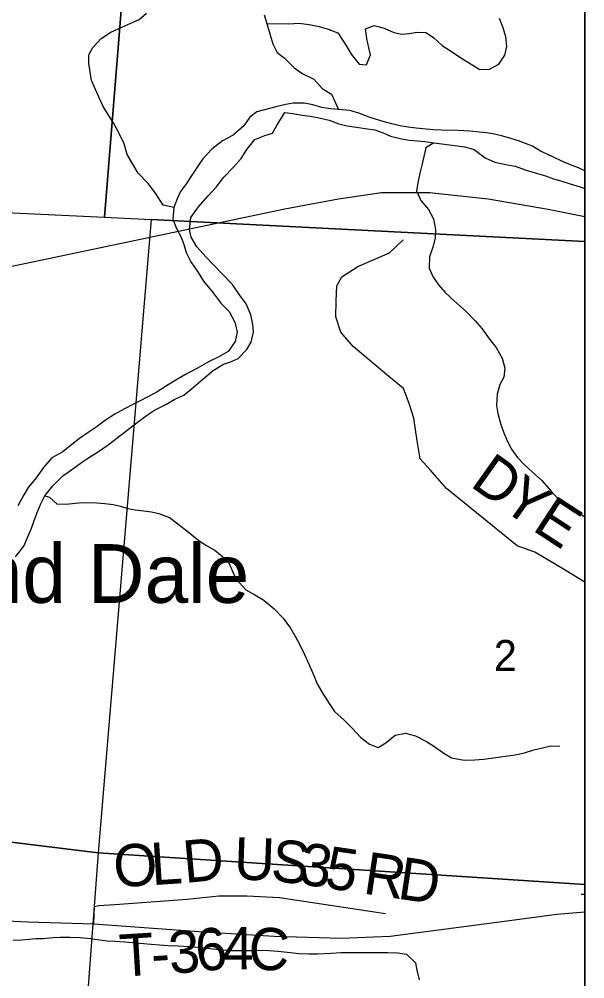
# Model space of a CAD drawing. Extents: x 5.6 to 39.6, y 0.7 to 22.7.
# Drawn here: x 14.292 to 15.052, y 19.81 to 21.1 of the extents above; entities that cross this region are included whole.
import ezdxf

# ---------------------------------------------------------------- set-up
doc = ezdxf.new("R2010")
doc.units = 0
doc.layers.add('Default', color=7, linetype='Continuous')
doc.layers.add('SH_Data', color=7, linetype='Continuous')

msp = doc.modelspace()

# ---------------------------------------------------------------- linework, layer by layer
at = {"layer": 'Default'}
for p, q in [((15.0518, 19.9373), (15.0518, 20.8015)), ((15.0518, 18.9873), (15.0518, 19.9373))]:
    msp.add_line(p, q, dxfattribs=at)
for points in [[(15.0518, 18.0251), (15.0518, 21.7074), (8.2518, 21.7074), (8.2518, 18.5322)], [(15.0518, 18.0251), (15.0518, 21.7074), (8.2518, 21.7074), (8.2518, 18.5322)], [(15.0518, 18.0251), (15.0518, 21.7074), (10.4881, 21.7074)], [(13.5074, 21.7074), (13.4593, 20.8788), (14.4061, 20.8339), (14.4767, 21.7074)], [(14.4767, 21.7074), (14.4061, 20.8339), (14.469, 20.831), (15.0518, 20.8015)], [(15.0518, 20.8015), (15.0518, 21.7074), (14.4767, 21.7074)], [(14.4994, 20.8472), (14.485, 20.8504), (14.4746, 20.8661), (14.4649, 20.8791), (14.4515, 20.8933), (14.4441, 20.9051), (14.4367, 20.9185), (14.4327, 20.9326), (14.426, 20.9463), (14.4186, 20.96), (14.4127, 20.9696), (14.4045, 20.9826), (14.3994, 20.9937), (14.3887, 21.0177), (14.3869, 21.0295), (14.3852, 21.0405), (14.3853, 21.0522), (14.3904, 21.062), (14.4019, 21.0744), (14.4148, 21.0829), (14.4297, 21.0892), (14.4414, 21.0947), (14.4529, 21.0999), (14.4628, 21.1081)], [(14.6206, 21.1061), (14.6246, 21.0942), (14.6286, 21.0805), (14.6326, 21.0672), (14.6381, 21.0554), (14.6479, 21.0481), (14.661, 21.0346), (14.673, 21.0269), (14.6876, 21.0195), (14.6989, 21.0072), (14.7113, 20.9995), (14.7208, 20.9789)], [(14.6246, 21.0942), (14.6541, 21.0939), (14.6674, 21.0948), (14.6813, 21.0931), (14.6949, 21.0903), (14.707, 21.0868), (14.7198, 21.0817), (14.7313, 21.0637), (14.7376, 21.053), (14.7485, 21.0396), (14.7583, 21.0387), (14.7637, 21.0523), (14.7616, 21.0618), (14.7587, 21.0743), (14.757, 21.0873), (14.7688, 21.0917), (14.782, 21.0881), (14.7951, 21.0822), (14.8057, 21.0802), (14.8156, 21.0808), (14.8266, 21.0826), (14.8379, 21.0824), (14.8484, 21.0755), (14.86, 21.0647), (14.8713, 21.0578), (14.8837, 21.0489), (14.9108, 21.0326), (14.9236, 21.0329), (14.9362, 21.0399), (14.9443, 21.0516), (14.9471, 21.0633), (14.9457, 21.0766), (14.9421, 21.0887), (14.9373, 21.1009)], [(15.0518, 20.8965), (15.0432, 20.9002), (15.0327, 20.9045), (15.0225, 20.9084), (15.0078, 20.9154), (14.9924, 20.9228), (14.9815, 20.9294), (14.9626, 20.9368), (14.9524, 20.94), (14.9415, 20.9428), (14.9302, 20.9456), (14.9196, 20.9472), (14.9097, 20.9481), (14.8973, 20.9498), (14.8814, 20.9507), (14.8594, 20.951), (14.8485, 20.9515), (14.8386, 20.9524), (14.825, 20.9537), (14.8144, 20.955), (14.8031, 20.957), (14.7925, 20.9594), (14.782, 20.9622), (14.7718, 20.9654), (14.762, 20.9685), (14.748, 20.974), (14.736, 20.9772), (14.7208, 20.9789), (14.7099, 20.9798), (14.6985, 20.9815), (14.6861, 20.985), (14.6748, 20.9871), (14.66, 20.9873), (14.6501, 20.9855), (14.6384, 20.983), (14.611, 20.9758), (14.6015, 20.9683), (14.5934, 20.9567), (14.5793, 20.9443), (14.5648, 20.9366), (14.5503, 20.9254), (14.5384, 20.9123), (14.5307, 20.9014), (14.5237, 20.8905)], [(14.2866, 20.3775), (14.2978, 20.3921), (14.3028, 20.4034), (14.3075, 20.4148), (14.311, 20.425), (14.3157, 20.437), (14.32, 20.448), (14.3262, 20.4596), (14.3366, 20.4728), (14.3504, 20.4866), (14.3618, 20.4945), (14.3752, 20.5045), (14.3848, 20.5108), (14.3981, 20.519), (14.4111, 20.5279), (14.4229, 20.5369), (14.4386, 20.5492), (14.452, 20.5596), (14.4627, 20.5675), (14.4733, 20.5745), (14.4886, 20.5823), (14.5008, 20.5894), (14.5129, 20.5949), (14.5229, 20.6031), (14.5382, 20.6162), (14.5523, 20.6281), (14.5661, 20.6367), (14.5756, 20.6396), (14.5858, 20.644), (14.5977, 20.6564), (14.6035, 20.6661), (14.6063, 20.6801), (14.6057, 20.69), (14.6028, 20.7029), (14.5966, 20.7178), (14.5876, 20.7297), (14.5783, 20.7434), (14.563, 20.7592), (14.5529, 20.7699), (14.5428, 20.7803), (14.5301, 20.7941), (14.5227, 20.8074), (14.5206, 20.8173), (14.5223, 20.8336), (14.5327, 20.8479), (14.5457, 20.8629), (14.5561, 20.8745), (14.5668, 20.888), (14.5795, 20.9011), (14.5899, 20.9131), (14.5976, 20.9251), (14.6083, 20.9383), (14.6216, 20.9438), (14.6319, 20.9471), (14.6385, 20.958), (14.6485, 20.9749), (14.6595, 20.9733), (14.6719, 20.9712), (14.6825, 20.9699), (14.6927, 20.9679), (14.7082, 20.9643), (14.721, 20.9596), (14.7323, 20.9568), (14.7448, 20.9551), (14.7565, 20.9534), (14.7697, 20.9514), (14.7806, 20.9475), (14.7904, 20.9428), (14.8036, 20.9396), (14.8157, 20.9375), (14.8267, 20.9366), (14.8369, 20.9358), (14.849, 20.9341)], [(14.849, 20.9341), (14.8383, 20.9274), (14.8327, 20.904), (14.83, 20.893), (14.8276, 20.8824), (14.8255, 20.8696), (14.8314, 20.8566), (14.8419, 20.8443), (14.8482, 20.8317), (14.851, 20.8177), (14.8505, 20.8063), (14.8481, 20.795), (14.843, 20.7806), (14.8424, 20.7655), (14.848, 20.7533), (14.855, 20.743), (14.864, 20.7326), (14.8767, 20.7211), (14.8925, 20.7072), (14.9044, 20.6946), (14.9138, 20.6838), (14.9238, 20.6701), (14.9328, 20.659), (14.9409, 20.6445), (14.9445, 20.6312), (14.9429, 20.619), (14.9375, 20.6093), (14.9339, 20.5964), (14.933, 20.5809), (14.9347, 20.5702), (14.9391, 20.5554), (14.9431, 20.5444), (14.9479, 20.5326), (14.9531, 20.5223), (14.9613, 20.5112), (14.9702, 20.5016), (14.9811, 20.492), (14.9942, 20.48), (15.0062, 20.4663), (15.0196, 20.4517), (15.0343, 20.442), (15.0467, 20.4343), (15.0518, 20.4314)], [(14.849, 20.9341), (14.8596, 20.9328), (14.8698, 20.9312), (14.8804, 20.9299), (14.8902, 20.9286), (14.903, 20.9251), (14.918, 20.9139), (14.9308, 20.908), (14.9478, 20.9044), (14.958, 20.9024), (14.9716, 20.8977), (14.9863, 20.8933), (14.9988, 20.8894), (15.0097, 20.8855), (15.0195, 20.8827), (15.0323, 20.8787), (15.0455, 20.8748), (15.0518, 20.8724)], [(14.5237, 20.8905), (14.5164, 20.8792), (14.5083, 20.8687), (14.5037, 20.8585), (14.4994, 20.8472), (14.498, 20.8316), (14.5028, 20.8187), (14.5095, 20.8061), (14.5131, 20.7962), (14.516, 20.7867), (14.5223, 20.7741), (14.532, 20.7596), (14.5394, 20.7481), (14.5521, 20.7324), (14.5629, 20.7182), (14.5737, 20.7075), (14.5815, 20.693), (14.5847, 20.6793), (14.5819, 20.6668), (14.5723, 20.6536), (14.5601, 20.6462), (14.5468, 20.6399), (14.5312, 20.631), (14.5144, 20.6222), (14.4999, 20.6136), (14.4896, 20.6073), (14.4755, 20.5984), (14.4645, 20.5928), (14.4542, 20.5873), (14.4443, 20.5821), (14.4329, 20.5766), (14.4199, 20.5695), (14.4062, 20.5602), (14.3962, 20.5528), (14.3856, 20.5457), (14.3726, 20.5368), (14.3623, 20.5286), (14.35, 20.5189), (14.3356, 20.5107), (14.324, 20.4976), (14.3144, 20.4837), (14.3037, 20.4706), (14.2979, 20.4608), (14.2897, 20.4461)], [(12.8355, 20.6493), (12.9056, 20.5902), (12.9607, 20.5632), (13.0172, 20.5443), (13.0844, 20.5361), (13.1261, 20.5361), (13.1871, 20.5436), (13.2806, 20.5642), (13.9828, 20.7053), (14.6487, 20.8453), (14.7209, 20.8587), (14.7785, 20.867), (14.8429, 20.867), (14.9217, 20.8586), (15.0024, 20.845), (15.0518, 20.8348)], [(15.0518, 20.8015), (14.469, 20.831), (14.3975, 19.9797), (15.0518, 19.9373)], [(15.0518, 20.3434), (15.0231, 20.3608), (14.9844, 20.3839), (14.961, 20.3925), (14.866, 20.4693), (14.8439, 20.4946), (14.8304, 20.5091), (14.8265, 20.5334), (14.8219, 20.5638), (14.8157, 20.5836), (14.8083, 20.6037), (14.7884, 20.6199), (14.7404, 20.6602), (14.7239, 20.6797), (14.7173, 20.6999), (14.7175, 20.7211), (14.7185, 20.7419), (14.7254, 20.754), (14.7467, 20.7678), (14.7893, 20.7863), (14.8076, 20.8035)], [(14.3262, 20.4596), (14.3323, 20.4577), (14.3424, 20.4484), (14.3586, 20.4486), (14.3719, 20.4503), (14.3817, 20.4506), (14.3957, 20.45), (14.4067, 20.4491), (14.418, 20.4479), (14.4279, 20.4458), (14.4377, 20.4427), (14.4475, 20.4407), (14.4592, 20.4394), (14.4694, 20.4381), (14.4792, 20.4357), (14.4935, 20.4306), (14.5048, 20.4221), (14.5186, 20.4113), (14.5333, 20.399), (14.5434, 20.3928), (14.5543, 20.3866), (14.5648, 20.3781), (14.5738, 20.3685), (14.5789, 20.3571), (14.583, 20.3476), (14.596, 20.3334), (14.6084, 20.3264), (14.6205, 20.3194), (14.6343, 20.3079), (14.6463, 20.2952), (14.656, 20.2818), (14.663, 20.27), (14.6682, 20.2601), (14.6752, 20.2463), (14.6811, 20.2322), (14.6874, 20.2181), (14.6922, 20.2071), (14.6999, 20.1929), (14.7089, 20.1792), (14.7152, 20.1696), (14.7283, 20.1581), (14.7388, 20.1477), (14.7507, 20.1347), (14.7623, 20.1258), (14.774, 20.1211), (14.7843, 20.1278), (14.7969, 20.1379), (14.8106, 20.1408), (14.8242, 20.1368), (14.8392, 20.1294), (14.849, 20.1232), (14.8621, 20.1136), (14.8727, 20.1074), (14.8897, 20.1045), (14.9033, 20.1047), (14.9162, 20.1057), (14.9321, 20.1078), (14.9446, 20.1095), (14.9583, 20.1116), (14.9708, 20.1141), (14.9834, 20.1182), (14.9948, 20.121), (15.0062, 20.1236), (15.0183, 20.123)], [(15.0518, 19.9373), (14.3975, 19.9797), (14.3249, 19.0118), (15.0518, 18.9873)], [(14.3917, 19.8843), (14.3929, 19.9076), (14.3985, 19.9088), (14.4202, 19.9104), (14.5174, 19.9176), (14.5599, 19.922), (14.5973, 19.9221), (14.6415, 19.9198), (14.7837, 19.8984)], [(15.047, 19.9241), (15.0518, 19.9244)], [(14.2089, 19.8917), (14.3032, 19.8871), (14.3917, 19.8843), (14.5392, 19.8735), (14.6344, 19.8676), (14.7245, 19.8652), (14.79, 19.8676), (14.8928, 19.8811), (14.9571, 19.8897), (15.0143, 19.8975), (15.0518, 19.9004)], [(14.2836, 19.8622), (14.2945, 19.8628), (14.3044, 19.8638), (14.3142, 19.8645), (14.3237, 19.8647), (14.337, 19.8661), (14.3464, 19.8663), (14.3597, 19.8665), (14.3733, 19.866), (14.3873, 19.8647), (14.3994, 19.8626), (14.41, 19.8617), (14.4198, 19.8609), (14.4334, 19.8603), (14.4482, 19.859), (14.4588, 19.8577), (14.469, 19.8568), (14.48, 19.8563), (14.4917, 19.8554), (14.5046, 19.8549), (14.5204, 19.8539), (14.531, 19.853), (14.5412, 19.8522), (14.5518, 19.8509), (14.5643, 19.8496), (14.5768, 19.8487), (14.59, 19.8485), (14.6041, 19.8487), (14.6158, 19.849), (14.6271, 19.8484), (14.6392, 19.8475), (14.6563, 19.8458), (14.6672, 19.8445), (14.6805, 19.844), (14.693, 19.8442), (14.7108, 19.8451), (14.724, 19.8457), (14.7354, 19.846), (14.7456, 19.8458), (14.7627, 19.8456), (14.7767, 19.8458), (14.7869, 19.8457), (14.8001, 19.8452), (14.8119, 19.8435), (14.8242, 19.832), (14.826, 19.8221), (14.8292, 19.8092)]]:
    msp.add_lwpolyline(points, dxfattribs=at)
for points in [[(13.4593, 20.8788), (14.4061, 20.8339), (14.469, 20.831), (14.3975, 19.9797), (13.3714, 20.1056)], [(13.3714, 20.1056), (14.3975, 19.9797), (14.3249, 19.0118), (13.3131, 19.1164)]]:
    msp.add_lwpolyline(points, close=True, dxfattribs=at)
at = {"layer": 'SH_Data'}
msp.add_line((15.0518, 21.7074), (15.0518, 14.7074), dxfattribs=at)

# ---------------------------------------------------------------- texts
at = {"layer": 'Default'}
for s, height, rotation, p in [('D', 0.0568, 324.5976, (14.8961, 20.4734)), ('Y', 0.0568, 324.6928, (14.9369, 20.4444)), ('E', 0.0568, 326.8323, (14.9796, 20.4142)), ('Richmond Dale', 0.078914, 0, (13.8794, 20.3157)), ('2', 0.0418, 0, (14.9294, 20.224)), ('O', 0.0568, 3.4591, (14.4198, 19.9332)), ('L', 0.0568, 3.8296, (14.4701, 19.9362)), ('D', 0.0568, 5.3966, (14.5142, 19.9392)), ('U', 0.0568, 357.9541, (14.5795, 19.9441)), ('S', 0.0568, 353.5079, (14.6283, 19.9424)), ('3', 0.0568, 351.6679, (14.6659, 19.9381)), ('5', 0.0568, 351.4909, (14.7005, 19.933)), ('R', 0.0568, 351.4912, (14.7524, 19.9253)), ('D', 0.0568, 351.4902, (14.7986, 19.9184)), ('3', 0.0568, 4.0699, (14.4942, 19.8171)), ('6', 0.0568, 5.8911, (14.5311, 19.8198)), ('4', 0.0568, 0.1067, (14.5644, 19.8233)), ('C', 0.0568, 357.3352, (14.5987, 19.8234)), ('T', 0.0568, 3.4929, (14.4279, 19.8131)), ('-', 0.0568, 3.5899, (14.4704, 19.8156))]:
    msp.add_text(s, height=height, rotation=rotation, dxfattribs=at).set_placement(p)

doc.saveas('drawing.dxf')
